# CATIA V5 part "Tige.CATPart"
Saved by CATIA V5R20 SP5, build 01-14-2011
Part number: Tige
Bounding box of the stored display mesh (mm): x 200 to 250, y -49.985 to 584.985, z -49.985 to 109.985
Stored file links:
  G:\IAO Final\Tige.CATPart
  G:\IAO Final\Assemblage Final.CATProduct
  G:\IAO Final\SKL Tige.CATPart
  G:\IAO Final\Roue.CATPart
  G:\IAO Final\Piece 2.CATPart
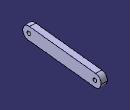
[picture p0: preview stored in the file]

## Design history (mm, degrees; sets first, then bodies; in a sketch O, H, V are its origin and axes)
External parameters (linked from other documents)
  `External.Rayon excentrique` = 15 mm
Set1
  Plane1: linked copy from another document
  Point1: linked copy from another document
  Line1: linked copy from another document
  Point2: linked copy from another document
Body1 (main body)
  Sketch1 on Plane1, origin (0, 0, 0), H (0, 1, 0), V (0, 0, 1)
    line L1 (-44.116, 115.261) -> (590.261, 44.116)
    line L2 (590.261, 44.116) -> (579.116, -55.261)
    line L3 (579.116, -55.261) -> (-55.261, 15.884)
    line L4 (-55.261, 15.884) -> (-44.116, 115.261)
    circle A1 centre (0, 60) radius 15
    point P5 (0, 60)
    circle A2 centre (535, 0) radius 15
    point P6 (535, 0)
    reference projected point E1 (0, 60) from Point1
    reference projected line E2 through (0, 0) direction (1, 0) from Line1
    reference projected point E3 (535, 0) from Point2
    length L4 = 100
    radius A2 = 15 {= `External.Rayon excentrique`}
    radius A1 = 15 {= `External.Rayon excentrique`}
    distance P5 L4 = 50
    distance P5 L1 = 50
    distance P6 L2 = 50
    distance P6 L1 = 50
    coincidence: P5 E1, P6 E2, P6 E3
    perpendicularity: L1 L2, L4 L3, L4 L1
  Pad1: profile Sketch1, direction (-1, 0, 0), length -200, opposite side length 250
  Point3: type Center, Curve edge [face of Pad1 from Sketch1.A2 | end face of Pad1]
  Fillet1: radius 50, on edge [face of Pad1 from Sketch1.L1 | face of Pad1 from Sketch1.L4]; edge [face of Pad1 from Sketch1.L4 | face of Pad1 from Sketch1.L3]; edge [face of Pad1 from Sketch1.L2 | face of Pad1 from Sketch1.L1]; edge [face of Pad1 from Sketch1.L3 | face of Pad1 from Sketch1.L2]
